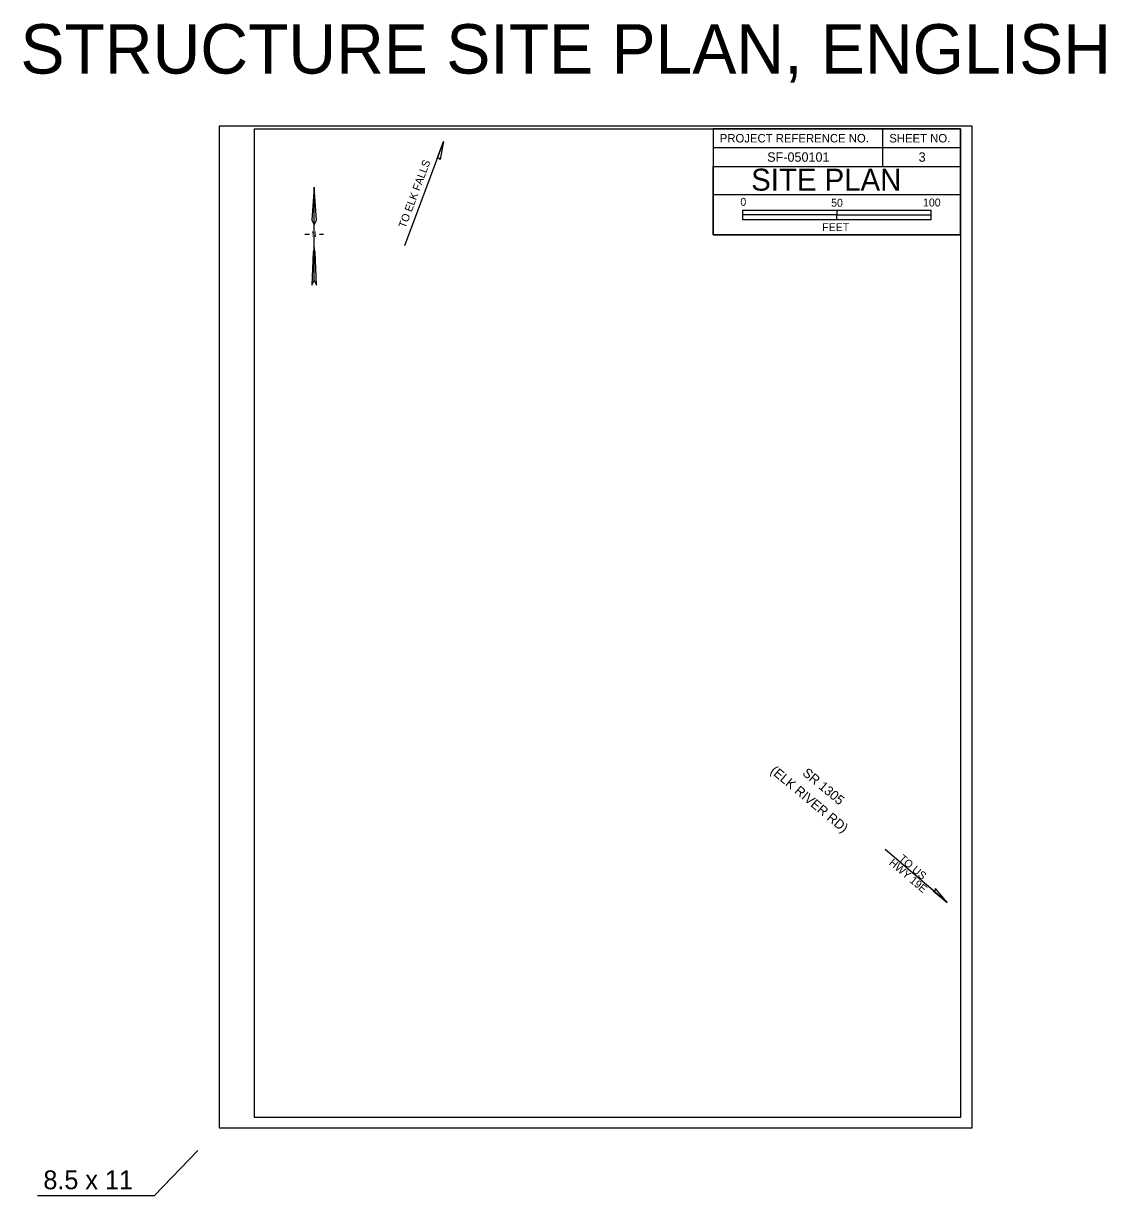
# Model space of a CAD drawing. Extents: x 1122794 to 1123368, y 901376 to 901999.
import ezdxf

# ---------------------------------------------------------------- set-up
doc = ezdxf.new("R2010")
doc.units = 0
for name, color, linetype in [('Boring Cell', 7, 'Continuous'), ('Default', 7, 'Continuous'), ('Misc Plan Tools Cell', 7, 'Continuous'), ('Prop Road Plan_ Boring - Alignment Tx', 7, 'Continuous'), ('Prop Road Plan_ Boring - Labels from Geopak', 7, 'Continuous'), ('Prop Road Plan_ Material - Contact (rock)', 7, 'Continuous'), ('Scratch_Level_1', 7, 'Continuous'), ('Scratch_Level_2', 7, 'Continuous')]:
    doc.layers.add(name, color=color, linetype=linetype)

msp = doc.modelspace()

# ---------------------------------------------------------------- linework, layer by layer
at = {"layer": 'Boring Cell'}
msp.add_lwpolyline([(1122897.69, 901412.36), (1123297.69, 901412.36), (1123297.69, 901944.36), (1122897.69, 901944.36)], close=True, dxfattribs=at)
at = {"layer": 'Default'}
for p, q in [((1123016.72, 901936.17), (1122996.06, 901880.8)), ((1123013.33, 901927.14), (1123016.72, 901936.17)), ((1123016.72, 901936.17), (1123014.95, 901926.72)), ((1123284.26, 901532.05), (1123251.33, 901560.17)), ((1123276.92, 901538.3), (1123284.26, 901532.05)), ((1123284.26, 901532.05), (1123278.13, 901539.46))]:
    msp.add_line(p, q, dxfattribs=at)
for centre, start, end in [((1123014.01, 901926.48), 14.06679, 134.81339), ((1123277.19, 901539.21), 254.23829, 14.9849)]:
    msp.add_arc(centre, 0.968, start, end, dxfattribs=at)
at = {"layer": 'Misc Plan Tools Cell'}
for p, q in [((1122948.09, 901861.91), (1122948.09, 901911.91)), ((1122943.09, 901886.91), (1122945.55, 901886.91)), ((1122950.83, 901886.91), (1122953.09, 901886.91))]:
    msp.add_line(p, q, dxfattribs=at)
for points in [[(1122948.09, 901911.91), (1122946.84, 901894.41), (1122948.09, 901891.91), (1122949.34, 901894.41)], [(1122948.02, 901879.93), (1122947.52, 901877.43), (1122946.77, 901859.93), (1122948.02, 901862.43), (1122949.27, 901859.93), (1122948.52, 901877.43)]]:
    msp.add_lwpolyline(points, close=True, dxfattribs=at)
at = {"layer": 'Prop Road Plan_ Boring - Labels from Geopak'}
for p, q in [((1123297.69, 901942.95), (1123297.69, 901942.95)), ((1122897.69, 901412.36), (1122897.69, 901412.36))]:
    msp.add_line(p, q, dxfattribs=at)
msp.add_lwpolyline([(1122801.16, 901376.41), (1122863.28, 901376.41), (1122886.24, 901400.4)], dxfattribs=at)
at = {"layer": 'Prop Road Plan_ Material - Contact (rock)'}
for p, q in [((1123250.02, 901942.95), (1123250.01, 901922.95)), ((1123159.96, 901932.95), (1123291.44, 901932.95)), ((1123159.96, 901908.05), (1123291.44, 901908.05))]:
    msp.add_line(p, q, dxfattribs=at)
for points in [[(1122916.44, 901942.95), (1123291.44, 901942.95), (1123291.44, 901417.95), (1122916.44, 901417.95)], [(1123159.96, 901886.63), (1123291.44, 901886.63), (1123291.44, 901942.95), (1123159.96, 901942.95)], [(1123159.96, 901922.95), (1123291.44, 901922.95), (1123291.44, 901942.95), (1123159.96, 901942.95)], [(1123159.96, 901922.95), (1123291.44, 901922.95), (1123291.44, 901886.63), (1123159.96, 901886.63)], [(1123175.7, 901899.68), (1123275.7, 901899.68), (1123275.7, 901894.68), (1123175.7, 901894.68)], [(1123175.7, 901899.68), (1123225.7, 901899.68), (1123225.7, 901897.18), (1123175.7, 901897.18)], [(1123225.7, 901897.18), (1123275.7, 901897.18), (1123275.7, 901894.68), (1123225.7, 901894.68)]]:
    msp.add_lwpolyline(points, close=True, dxfattribs=at)
at = {"layer": 'Scratch_Level_1'}
msp.add_lwpolyline([(1122916.44, 901942.95), (1123159.96, 901942.95), (1123159.96, 901886.63), (1123291.44, 901886.63), (1123291.44, 901417.95), (1122916.44, 901417.95)], close=True, dxfattribs=at)

# ---------------------------------------------------------------- texts
at = {"layer": 'Default'}
for s, rotation, p in [('TO ELK FALLS', 69.53701, (1122996.61, 901889.87)), ('HWY 19E', 319.51436, (1123253.1, 901552.54)), ('TO US', 319.51436, (1123258.3, 901554.76))]:
    msp.add_text(s, height=4.125, rotation=rotation, dxfattribs=at).set_placement(p)
at = {"layer": 'Misc Plan Tools Cell'}
msp.add_text('N', height=3, rotation=360, dxfattribs=at).set_placement((1122946.52, 901885.41))
at = {"layer": 'Prop Road Plan_ Boring - Alignment Tx'}
for s, p in [('(ELK RIVER RD)', (1123190, 901601.31)), ('SR 1305', (1123207.08, 901600.11))]:
    msp.add_text(s, height=5, rotation=320.22769, dxfattribs=at).set_placement(p)
at = {"layer": 'Prop Road Plan_ Boring - Labels from Geopak'}
msp.add_text('8.5 x 11', height=10, dxfattribs=at).set_placement((1122804.23, 901379.76))
at = {"layer": 'Prop Road Plan_ Material - Contact (rock)'}
for s, height, p in [('PROJECT REFERENCE NO.', 4.5, (1123163.52, 901935.7)), ('SHEET NO.', 4.5, (1123253.58, 901935.7)), ('SF-050101', 5, (1123188.74, 901925.45)), ('3', 5, (1123269.16, 901925.45)), ('0', 4.2, (1123174.49, 901902.06)), ('50', 4.2, (1123222.7, 901901.57)), ('100', 4.2, (1123271.48, 901901.71)), ('FEET', 4.2, (1123217.95, 901888.59))]:
    msp.add_text(s, height=height, dxfattribs=at).set_placement(p)
msp.add_text('SITE PLAN', height=11.667, rotation=360, dxfattribs=at).set_placement((1123180.22, 901910.09))
at = {"layer": 'Scratch_Level_2'}
msp.add_text('STRUCTURE SITE PLAN, ENGLISH', height=26.2501, dxfattribs=at).set_placement((1122792.04, 901972.27))

doc.saveas('drawing.dxf')
